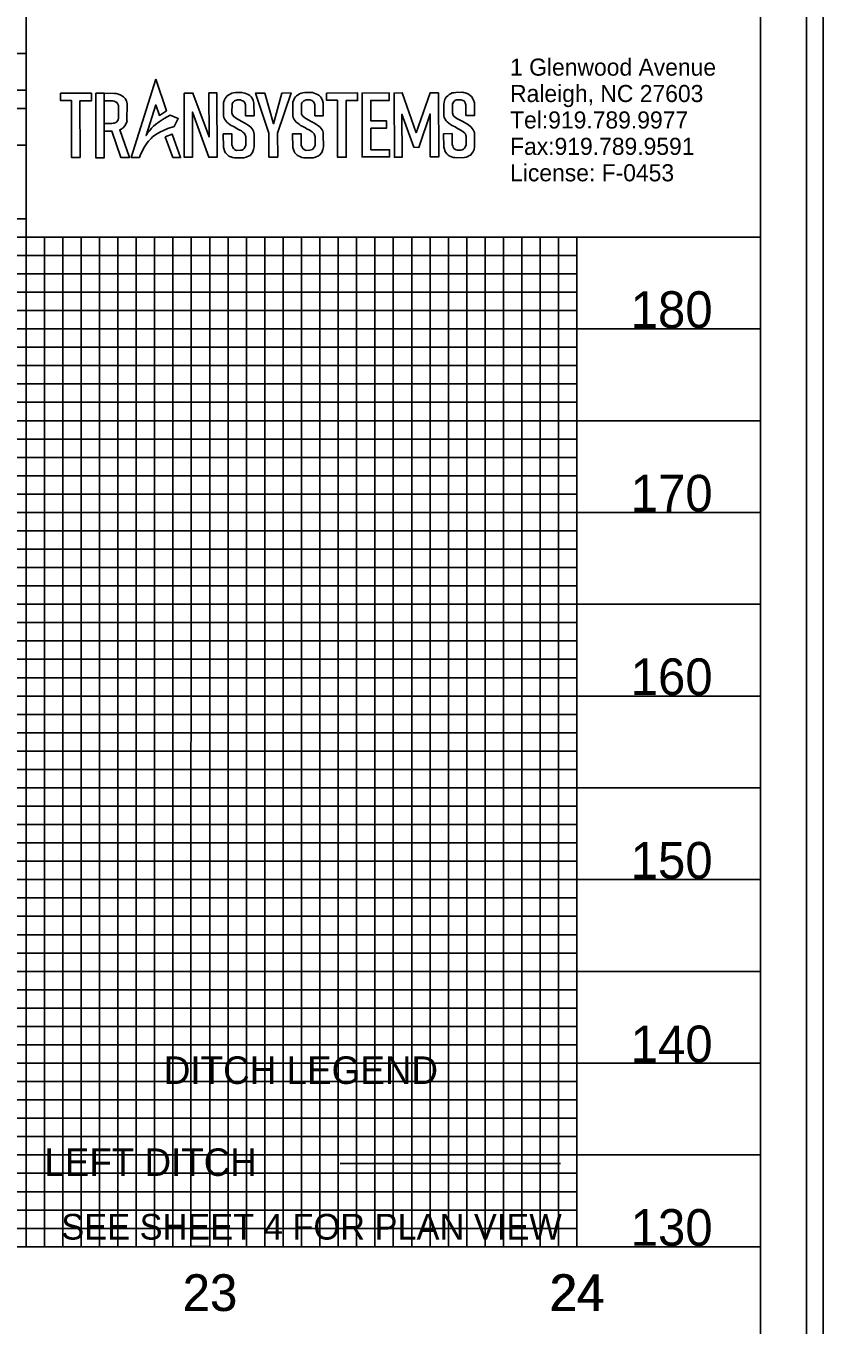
# Model space of a CAD drawing. Extents: x 1779926 to 1781610, y 620464 to 621564.
# Drawn here: x 1781392.9 to 1781610, y 621017.9 to 621371.7 of the extents above; entities that cross this region are included whole.
import ezdxf

# ---------------------------------------------------------------- set-up
doc = ezdxf.new("R2010")
doc.units = 0
for name, color, linetype in [('Default', 7, 'Continuous'), ('Exist Vertical Profile Horizontal Axis Label Major', 7, 'Continuous'), ('Exist Vertical Profile Vertical Axis Label', 7, 'Continuous'), ('Old_Level_2', 7, 'Continuous'), ('Old_Level_58', 7, 'Continuous'), ('Prop DSN Text', 7, 'Continuous'), ('Prop Grid Mask', 7, 'Continuous'), ('Prop PFL Ditch Label CELL', 7, 'Continuous'), ('Scratch_Level_0', 7, 'Continuous'), ('Sheet DOT Grid CELL', 7, 'Continuous'), ('Sheet Layout Profile Border Port 1', 7, 'Continuous'), ('Sheet Plot Border Inside CELL', 7, 'Continuous'), ('Sheet Plot Border Outside CELL', 7, 'Continuous'), ('Sheet Profile CELL', 7, 'Continuous'), ('Sheet Profile Grid Major CELL', 7, 'Continuous'), ('Sheet Profile Grid Middle CELL', 7, 'Continuous'), ('Sheet Profile Grid Minor CELL', 7, 'Continuous')]:
    doc.layers.add(name, color=color, linetype=linetype)

msp = doc.modelspace()

# ---------------------------------------------------------------- linework, layer by layer
at = {"layer": 'Default'}
for points in [[(1781428.25, 621357.21), (1781421.58, 621335.88), (1781423.81, 621335.89), (1781424.15, 621336.73), (1781424.72, 621337.89), (1781425.03, 621338.52), (1781425.41, 621339.06), (1781425.93, 621339.82), (1781426.26, 621340.28), (1781426.64, 621340.68), (1781427.02, 621341.07), (1781427.51, 621341.57), (1781427.92, 621341.84), (1781428.33, 621342.17), (1781428.89, 621342.49), (1781429.38, 621342.77), (1781430.6, 621343.34), (1781431.6, 621343.75), (1781433.24, 621344.31), (1781434.38, 621346.45), (1781432.2, 621347.41), (1781430.57, 621346.52), (1781429.19, 621345.62), (1781428.21, 621344.82), (1781427.69, 621344.39), (1781427.15, 621343.83), (1781426.62, 621343.26), (1781426.22, 621342.83), (1781425.84, 621342.19), (1781425.63, 621341.83), (1781428.26, 621350.2), (1781429.26, 621347.31), (1781431.16, 621348.57)], [(1781402.29, 621353.37), (1781410.75, 621353.37), (1781410.75, 621351.3), (1781407.64, 621351.3), (1781407.66, 621335.88), (1781405.31, 621335.87), (1781405.29, 621351.4), (1781402.32, 621351.4)], [(1781411.91, 621353.36), (1781414.22, 621353.36), (1781414.24, 621335.8), (1781411.92, 621335.8)], [(1781414.22, 621351.28), (1781416.61, 621351.28), (1781416.91, 621351.23), (1781417.32, 621351.07), (1781417.64, 621350.85), (1781417.87, 621350.58), (1781418.03, 621350.25), (1781418.15, 621349.99), (1781418.15, 621349.41), (1781418.16, 621346.92), (1781418.1, 621346.59), (1781418.01, 621346.14), (1781417.88, 621345.85), (1781417.68, 621345.59), (1781417.41, 621345.38), (1781416.99, 621345.23), (1781416.66, 621345.18), (1781416.34, 621345.14), (1781414.23, 621345.13), (1781414.24, 621343.02), (1781416.35, 621343.03), (1781418.72, 621335.87), (1781421.13, 621335.9), (1781418.48, 621343.44), (1781418.86, 621343.57), (1781419.4, 621343.97), (1781419.89, 621344.5), (1781420.23, 621345.14), (1781420.45, 621345.77), (1781420.43, 621345.96), (1781420.48, 621350.52), (1781420.27, 621351.27), (1781419.91, 621351.94), (1781419.5, 621352.42), (1781418.8, 621352.89), (1781418.12, 621353.12), (1781417.45, 621353.34), (1781417.04, 621353.34), (1781414.22, 621353.36)], [(1781436.02, 621353.4), (1781436.03, 621335.94), (1781438.27, 621335.94), (1781438.26, 621348.22), (1781442.71, 621335.92), (1781444.96, 621335.95), (1781444.94, 621353.45), (1781442.76, 621353.45), (1781442.78, 621341.47), (1781438.37, 621353.4)], [(1781452.72, 621347.23), (1781455.03, 621347.23), (1781455.02, 621350.71), (1781454.83, 621351.41), (1781454.55, 621352), (1781454.25, 621352.39), (1781453.88, 621352.74), (1781453.44, 621353.03), (1781453.01, 621353.2), (1781453.01, 621353.2), (1781452.55, 621353.39), (1781452.07, 621353.52), (1781451.75, 621353.6), (1781450, 621353.56), (1781449.47, 621353.47), (1781449.02, 621353.39), (1781448.55, 621353.15), (1781448.15, 621352.94), (1781447.76, 621352.65), (1781447.45, 621352.34), (1781447.2, 621351.98), (1781447.01, 621351.58), (1781446.75, 621350.88), (1781446.7, 621350.37), (1781446.7, 621347.2), (1781446.82, 621346.72), (1781447.05, 621346.23), (1781447.34, 621345.82), (1781447.63, 621345.51), (1781448.08, 621345.16), (1781448.54, 621344.81), (1781448.82, 621344.59), (1781449.3, 621344.37), (1781449.79, 621344.14), (1781450.18, 621343.89), (1781450.62, 621343.6), (1781451.15, 621343.34), (1781451.58, 621343.12), (1781452.01, 621342.8), (1781452.32, 621342.51), (1781452.57, 621342.27), (1781452.72, 621341.79), (1781452.82, 621341.49), (1781452.78, 621339.25), (1781452.62, 621338.77), (1781452.38, 621338.35), (1781452.05, 621338.06), (1781451.69, 621337.9), (1781451.35, 621337.83), (1781450.39, 621337.81), (1781450.07, 621337.9), (1781449.74, 621338.09), (1781449.41, 621338.28), (1781449.27, 621338.62), (1781449.13, 621338.95), (1781449.01, 621339.22), (1781448.98, 621342.33), (1781446.64, 621342.31), (1781446.68, 621338.6), (1781446.8, 621338.31), (1781447.07, 621337.45), (1781447.24, 621337.16), (1781447.5, 621336.84), (1781447.88, 621336.47), (1781448.18, 621336.27), (1781448.62, 621336.09), (1781448.78, 621336.02), (1781449.2, 621335.84), (1781449.74, 621335.79), (1781450.13, 621335.75), (1781452.27, 621335.8), (1781452.87, 621335.95), (1781453.69, 621336.32), (1781453.97, 621336.45), (1781454.6, 621337.24), (1781454.93, 621338.02), (1781455.08, 621338.73), (1781455.03, 621342.16), (1781455.02, 621342.63), (1781454.89, 621343), (1781454.7, 621343.36), (1781454.16, 621344.12), (1781453.45, 621344.67), (1781452.48, 621345.25), (1781451.73, 621345.7), (1781450.27, 621346.46), (1781449.52, 621347.03), (1781449.19, 621347.45), (1781449.11, 621347.73), (1781449.03, 621348.01), (1781449.08, 621350.45), (1781449.2, 621350.7), (1781449.33, 621350.96), (1781449.51, 621351.11), (1781449.74, 621351.3), (1781450, 621351.41), (1781450.25, 621351.52), (1781450.4, 621351.49), (1781450.42, 621351.56), (1781451.38, 621351.55), (1781451.65, 621351.44), (1781451.93, 621351.33), (1781452.21, 621351.22), (1781452.34, 621351.03), (1781452.52, 621350.75), (1781452.61, 621350.47), (1781452.71, 621350.2), (1781452.7, 621349.89)], [(1781457.99, 621353.41), (1781455.45, 621353.41), (1781459.07, 621342.52), (1781459.1, 621335.98), (1781461.49, 621335.99), (1781461.46, 621342.48), (1781465.12, 621353.45), (1781462.62, 621353.38), (1781460.31, 621345.04)], [(1781471.59, 621347.24), (1781473.9, 621347.25), (1781473.89, 621350.72), (1781473.7, 621351.43), (1781473.42, 621352.02), (1781473.12, 621352.41), (1781472.75, 621352.76), (1781472.31, 621353.04), (1781471.88, 621353.22), (1781471.88, 621353.22), (1781471.43, 621353.41), (1781470.94, 621353.53), (1781470.62, 621353.61), (1781468.87, 621353.58), (1781468.34, 621353.49), (1781467.89, 621353.41), (1781467.43, 621353.17), (1781467.02, 621352.96), (1781466.63, 621352.67), (1781466.32, 621352.36), (1781466.08, 621351.99), (1781465.88, 621351.6), (1781465.63, 621350.9), (1781465.58, 621350.39), (1781465.58, 621347.22), (1781465.69, 621346.74), (1781465.92, 621346.25), (1781466.21, 621345.84), (1781466.51, 621345.53), (1781466.96, 621345.18), (1781467.41, 621344.83), (1781467.69, 621344.61), (1781468.18, 621344.39), (1781468.66, 621344.16), (1781469.05, 621343.91), (1781469.49, 621343.62), (1781470.02, 621343.36), (1781470.45, 621343.14), (1781470.88, 621342.82), (1781471.19, 621342.53), (1781471.44, 621342.29), (1781471.59, 621341.81), (1781471.69, 621341.51), (1781471.65, 621339.27), (1781471.49, 621338.79), (1781471.25, 621338.37), (1781470.92, 621338.08), (1781470.56, 621337.92), (1781470.22, 621337.84), (1781469.26, 621337.82), (1781468.94, 621337.91), (1781468.61, 621338.11), (1781468.28, 621338.3), (1781468.14, 621338.64), (1781468, 621338.97), (1781467.88, 621339.24), (1781467.85, 621342.35), (1781465.51, 621342.32), (1781465.55, 621338.61), (1781465.67, 621338.33), (1781465.94, 621337.47), (1781466.12, 621337.18), (1781466.37, 621336.86), (1781466.75, 621336.48), (1781467.05, 621336.29), (1781467.49, 621336.11), (1781467.65, 621336.04), (1781468.08, 621335.86), (1781468.61, 621335.81), (1781469, 621335.77), (1781471.15, 621335.82), (1781471.74, 621335.96), (1781472.57, 621336.34), (1781472.85, 621336.46), (1781473.47, 621337.25), (1781473.8, 621338.04), (1781473.96, 621338.75), (1781473.9, 621342.17), (1781473.9, 621342.65), (1781473.76, 621343.02), (1781473.57, 621343.38), (1781473.03, 621344.13), (1781472.33, 621344.69), (1781471.35, 621345.27), (1781470.61, 621345.71), (1781469.14, 621346.48), (1781468.39, 621347.04), (1781468.06, 621347.46), (1781467.98, 621347.75), (1781467.91, 621348.03), (1781467.95, 621350.46), (1781468.08, 621350.72), (1781468.2, 621350.97), (1781468.38, 621351.13), (1781468.61, 621351.32), (1781468.87, 621351.43), (1781469.13, 621351.54), (1781469.27, 621351.51), (1781469.29, 621351.58), (1781470.25, 621351.57), (1781470.52, 621351.46), (1781470.8, 621351.35), (1781471.08, 621351.24), (1781471.21, 621351.04), (1781471.39, 621350.77), (1781471.49, 621350.49), (1781471.58, 621350.21), (1781471.57, 621349.91)], [(1781474.74, 621353.43), (1781483.21, 621353.44), (1781483.21, 621351.37), (1781480.1, 621351.36), (1781480.12, 621335.94), (1781477.77, 621335.94), (1781477.75, 621351.47), (1781474.78, 621351.46)], [(1781491.82, 621353.44), (1781484.43, 621353.43), (1781484.45, 621336.01), (1781491.92, 621336.01), (1781491.92, 621337.98), (1781486.87, 621337.98), (1781486.87, 621343.82), (1781491.08, 621343.83), (1781491.08, 621345.9), (1781486.83, 621345.9), (1781486.83, 621351.4), (1781491.84, 621351.4)], [(1781499.19, 621342.59), (1781495.38, 621353.51), (1781493.17, 621353.41), (1781493.25, 621335.95), (1781495.36, 621335.96), (1781495.31, 621347.63), (1781498.57, 621338.65), (1781499.92, 621338.61), (1781502.99, 621347.75), (1781503.03, 621336.02), (1781505.32, 621336.03), (1781505.25, 621353.45), (1781502.95, 621353.44)], [(1781512.72, 621347.28), (1781515.03, 621347.28), (1781515.03, 621350.76), (1781514.83, 621351.47), (1781514.55, 621352.06), (1781514.25, 621352.45), (1781513.88, 621352.8), (1781513.44, 621353.08), (1781513.02, 621353.26), (1781513.02, 621353.26), (1781512.56, 621353.45), (1781512.08, 621353.57), (1781511.76, 621353.65), (1781510.01, 621353.61), (1781509.48, 621353.52), (1781509.02, 621353.45), (1781508.56, 621353.21), (1781508.15, 621352.99), (1781507.76, 621352.71), (1781507.45, 621352.4), (1781507.21, 621352.03), (1781507.01, 621351.64), (1781506.76, 621350.94), (1781506.71, 621350.42), (1781506.71, 621347.26), (1781506.82, 621346.78), (1781507.05, 621346.29), (1781507.34, 621345.87), (1781507.64, 621345.57), (1781508.09, 621345.22), (1781508.54, 621344.87), (1781508.83, 621344.65), (1781509.31, 621344.42), (1781509.79, 621344.2), (1781510.18, 621343.95), (1781510.62, 621343.66), (1781511.15, 621343.39), (1781511.58, 621343.17), (1781512.01, 621342.86), (1781512.32, 621342.56), (1781512.57, 621342.33), (1781512.73, 621341.85), (1781512.82, 621341.55), (1781512.79, 621339.31), (1781512.62, 621338.83), (1781512.38, 621338.41), (1781512.05, 621338.12), (1781511.7, 621337.95), (1781511.36, 621337.88), (1781510.39, 621337.86), (1781510.07, 621337.95), (1781509.74, 621338.15), (1781509.41, 621338.34), (1781509.27, 621338.67), (1781509.13, 621339.01), (1781509.02, 621339.28), (1781508.98, 621342.39), (1781506.64, 621342.36), (1781506.69, 621338.65), (1781506.8, 621338.37), (1781507.07, 621337.51), (1781507.25, 621337.21), (1781507.5, 621336.9), (1781507.88, 621336.52), (1781508.19, 621336.33), (1781508.62, 621336.15), (1781508.78, 621336.08), (1781509.21, 621335.9), (1781509.74, 621335.85), (1781510.14, 621335.81), (1781512.28, 621335.86), (1781512.87, 621336), (1781513.7, 621336.38), (1781513.98, 621336.5), (1781514.6, 621337.29), (1781514.93, 621338.08), (1781515.09, 621338.79), (1781515.04, 621342.21), (1781515.03, 621342.68), (1781514.9, 621343.06), (1781514.71, 621343.41), (1781514.17, 621344.17), (1781513.46, 621344.73), (1781512.48, 621345.31), (1781511.74, 621345.75), (1781510.28, 621346.52), (1781509.52, 621347.08), (1781509.19, 621347.5), (1781509.12, 621347.79), (1781509.04, 621348.07), (1781509.08, 621350.5), (1781509.21, 621350.76), (1781509.33, 621351.01), (1781509.51, 621351.16), (1781509.74, 621351.36), (1781510, 621351.47), (1781510.26, 621351.58), (1781510.41, 621351.55), (1781510.42, 621351.62), (1781511.38, 621351.6), (1781511.66, 621351.49), (1781511.93, 621351.39), (1781512.21, 621351.28), (1781512.34, 621351.08), (1781512.53, 621350.8), (1781512.62, 621350.53), (1781512.71, 621350.25), (1781512.7, 621349.95)], [(1781430.86, 621341.51), (1781432.78, 621342.27), (1781435.04, 621335.84), (1781432.94, 621335.91)]]:
    msp.add_lwpolyline(points, close=True, dxfattribs=at)
at = {"layer": 'Old_Level_58'}
msp.add_lwpolyline([(1781392.96, 621378.13), (1781592.95, 621378.13), (1781592.95, 621314.19), (1781392.96, 621314.19)], close=True, dxfattribs=at)
at = {"layer": 'Prop Grid Mask'}
for points in [[(1781392.96, 621099.19), (1781542.96, 621099.19), (1781542.96, 621074.19), (1781392.96, 621074.19)], [(1781392.96, 621074.19), (1781542.96, 621074.19), (1781542.96, 621049.19), (1781392.96, 621049.19)], [(1781542.96, 621049.19), (1781397.96, 621049.19), (1781397.96, 621039.19), (1781542.96, 621039.19)]]:
    msp.add_lwpolyline(points, close=True, dxfattribs=at)
at = {"layer": 'Prop PFL Ditch Label CELL'}
msp.add_line((1781478.51, 621061.89), (1781538.51, 621061.89), dxfattribs=at)
msp.add_line((1781478.51, 621061.89), (1781538.51, 621061.89), dxfattribs=at)
at = {"layer": 'Scratch_Level_0'}
msp.add_lwpolyline([(1780142.96, 621039.18), (1780142.96, 621239.19), (1780092.96, 621239.19), (1780092.96, 621264.19), (1780142.96, 621289.19), (1780142.96, 621539.18), (1781392.96, 621539.18), (1781392.96, 621314.18), (1781542.96, 621314.18), (1781542.96, 621039.18)], close=True, dxfattribs=at)
at = {"layer": 'Sheet DOT Grid CELL'}
for p, q in [((1781392.96, 621039.19), (1781392.96, 621401.64)), ((1781442.96, 621039.19), (1781442.96, 621314.19)), ((1781492.96, 621039.19), (1781492.96, 621314.19)), ((1781542.96, 621039.19), (1781542.96, 621314.19)), ((1781592.96, 621289.19), (1780092.96, 621289.19)), ((1781592.96, 621239.19), (1780092.96, 621239.19)), ((1781592.96, 621189.19), (1780092.96, 621189.19)), ((1781592.96, 621139.19), (1780092.96, 621139.19)), ((1781592.96, 621089.19), (1780092.96, 621089.19))]:
    msp.add_line(p, q, dxfattribs=at)
at = {"layer": 'Sheet Layout Profile Border Port 1'}
msp.add_lwpolyline([(1780142.96, 621378.14), (1780142.96, 621039.19), (1781542.96, 621039.19), (1781542.96, 621314.19)], dxfattribs=at)
at = {"layer": 'Sheet Plot Border Inside CELL'}
msp.add_lwpolyline([(1779938.96, 620486.64), (1781605.46, 620486.64), (1781605.46, 621541.74), (1779938.96, 621541.74)], close=True, dxfattribs=at)
at = {"layer": 'Sheet Plot Border Outside CELL'}
msp.add_lwpolyline([(1779925.96, 620464.19), (1781609.96, 620464.19), (1781609.96, 621564.19), (1779925.96, 621564.19)], close=True, dxfattribs=at)
at = {"layer": 'Sheet Profile CELL'}
msp.add_line((1780092.96, 621039.19), (1781592.96, 621039.19), dxfattribs=at)
msp.add_lwpolyline([(1781592.96, 621539.19), (1780092.96, 621539.19), (1780092.96, 620489.19), (1781592.96, 620489.19)], close=True, dxfattribs=at)
at = {"layer": 'Sheet Profile Grid Major CELL'}
for points in [[(1781142.96, 621039.19), (1781192.96, 621039.19), (1781192.96, 621539.19), (1781242.96, 621539.19), (1781242.96, 621039.19), (1781292.96, 621039.19), (1781292.96, 621539.19), (1781342.96, 621539.19), (1781342.96, 621039.19), (1781392.96, 621039.19), (1781392.96, 621539.19), (1781419.26, 621539.19)], [(1781542.96, 621314.19), (1781542.96, 621039.19), (1781592.96, 621039.19), (1781592.96, 621389.19)], [(1781392.91, 621339.19), (1780092.96, 621339.19), (1780092.96, 621289.19), (1781592.96, 621289.19)], [(1781442.96, 621314.19), (1781442.96, 621039.19), (1781492.96, 621039.19), (1781492.96, 621039.19), (1781492.96, 621314.19)], [(1781592.96, 621239.19), (1780092.96, 621239.19), (1780092.96, 621189.19), (1781592.96, 621189.19)], [(1781592.96, 621139.19), (1780092.96, 621139.19), (1780092.96, 621139.19), (1780092.96, 621089.19), (1781592.96, 621089.19)]]:
    msp.add_lwpolyline(points, dxfattribs=at)
at = {"layer": 'Sheet Profile Grid Middle CELL'}
for points in [[(1781117.96, 621539.19), (1781167.96, 621539.19), (1781167.96, 621039.19), (1781217.96, 621039.19), (1781217.96, 621539.19), (1781267.96, 621539.19), (1781267.96, 621039.19), (1781317.96, 621039.19), (1781317.96, 621539.19), (1781367.96, 621539.19), (1781367.96, 621039.19), (1781417.96, 621039.19), (1781417.96, 621314.19)], [(1781392.91, 621364.19), (1780092.96, 621364.19), (1780092.96, 621314.19), (1781417.96, 621314.19)], [(1781417.96, 621314.19), (1781592.96, 621314.19)], [(1781417.96, 621301.99), (1781417.96, 621039.19), (1781467.96, 621039.19), (1781467.96, 621314.19)], [(1781467.96, 621301.99), (1781467.96, 621039.19), (1781517.96, 621039.19), (1781517.96, 621314.19)], [(1781592.96, 621264.19), (1780092.96, 621264.19), (1780092.96, 621214.19), (1781592.96, 621214.19)], [(1781592.96, 621164.19), (1780092.96, 621164.19), (1780092.96, 621114.19), (1781592.96, 621114.19)], [(1781592.96, 621064.19), (1780092.96, 621064.19)]]:
    msp.add_lwpolyline(points, dxfattribs=at)
at = {"layer": 'Sheet Profile Grid Minor CELL'}
for p, q in [((1781392.96, 621354.19), (1780142.96, 621354.19)), ((1780142.96, 621349.19), (1781392.96, 621349.19)), ((1781542.96, 621304.19), (1780142.96, 621304.19)), ((1780142.96, 621299.19), (1781542.96, 621299.19)), ((1781542.96, 621294.19), (1780142.96, 621294.19)), ((1780142.96, 621284.19), (1781542.96, 621284.19)), ((1781542.96, 621279.19), (1780142.96, 621279.19)), ((1780142.96, 621274.19), (1781542.96, 621274.19)), ((1781542.96, 621269.19), (1780142.96, 621269.19)), ((1780142.96, 621259.19), (1781542.96, 621259.19)), ((1781542.96, 621254.19), (1780142.96, 621254.19)), ((1780142.96, 621249.19), (1781542.96, 621249.19)), ((1781542.96, 621244.19), (1780142.96, 621244.19)), ((1780142.96, 621234.19), (1781542.96, 621234.19)), ((1781542.96, 621229.19), (1780142.96, 621229.19)), ((1780142.96, 621224.19), (1781542.96, 621224.19)), ((1781542.96, 621219.19), (1780142.96, 621219.19)), ((1780142.96, 621209.19), (1781542.96, 621209.19)), ((1781542.96, 621204.19), (1780142.96, 621204.19)), ((1780142.96, 621199.19), (1781542.96, 621199.19)), ((1781542.96, 621194.19), (1780142.96, 621194.19)), ((1780142.96, 621184.19), (1781542.96, 621184.19)), ((1781542.96, 621179.19), (1780142.96, 621179.19)), ((1780142.96, 621174.19), (1781542.96, 621174.19)), ((1781542.96, 621169.19), (1780142.96, 621169.19)), ((1780142.96, 621159.19), (1781542.96, 621159.19)), ((1781542.96, 621154.19), (1780142.96, 621154.19)), ((1781542.96, 621149.19), (1780142.96, 621149.19)), ((1781542.96, 621144.19), (1780142.96, 621144.19)), ((1780142.96, 621134.19), (1781542.96, 621134.19)), ((1781542.96, 621129.19), (1780142.96, 621129.19)), ((1780142.96, 621124.19), (1781542.96, 621124.19)), ((1781542.96, 621119.19), (1780142.96, 621119.19)), ((1780142.96, 621109.19), (1781542.96, 621109.19)), ((1781542.96, 621104.19), (1780142.96, 621104.19)), ((1780142.96, 621099.19), (1781542.96, 621099.19)), ((1781542.96, 621094.19), (1780142.96, 621094.19)), ((1780142.96, 621084.19), (1781542.96, 621084.19)), ((1781542.96, 621079.19), (1780142.96, 621079.19)), ((1780142.96, 621074.19), (1781542.96, 621074.19)), ((1781542.96, 621069.19), (1780142.96, 621069.19)), ((1780142.96, 621059.19), (1781542.96, 621059.19)), ((1781542.96, 621054.19), (1780142.96, 621054.19)), ((1780142.96, 621049.19), (1781542.96, 621049.19))]:
    msp.add_line(p, q, dxfattribs=at)
for points in [[(1781392.91, 621319.19), (1780142.96, 621319.19), (1780142.96, 621309.19), (1781542.96, 621309.19)], [(1781397.96, 621314.19), (1781397.96, 621039.19), (1781402.96, 621039.19), (1781402.96, 621314.19)], [(1781407.96, 621314.19), (1781407.96, 621039.19), (1781412.96, 621039.19), (1781412.96, 621314.19)], [(1781422.96, 621314.19), (1781422.96, 621039.19), (1781422.96, 621039.19), (1781427.96, 621039.19), (1781432.96, 621039.19), (1781432.96, 621314.19)], [(1781427.96, 621314.19), (1781427.96, 621039.19)], [(1781437.94, 621314.19), (1781437.86, 621039.24), (1781442.86, 621039.24), (1781447.96, 621039.19), (1781447.96, 621314.19)], [(1781447.96, 621301.99), (1781447.96, 621039.19), (1781452.96, 621039.19), (1781452.96, 621314.19)], [(1781457.96, 621314.19), (1781457.96, 621039.19), (1781462.96, 621039.19), (1781462.96, 621314.19)], [(1781472.96, 621314.19), (1781472.96, 621039.19), (1781477.96, 621039.19), (1781477.96, 621314.19)], [(1781482.96, 621314.19), (1781482.96, 621039.19), (1781487.96, 621039.19), (1781487.96, 621314.19)], [(1781497.96, 621314.19), (1781497.96, 621039.19), (1781502.96, 621039.19), (1781502.96, 621314.19)], [(1781507.96, 621314.19), (1781507.96, 621039.19), (1781512.96, 621039.19), (1781512.96, 621314.19)], [(1781522.96, 621314.19), (1781522.96, 621039.19), (1781527.96, 621039.19), (1781527.96, 621314.19)], [(1781532.96, 621314.19), (1781532.96, 621039.19), (1781537.96, 621039.19), (1781537.96, 621314.19)], [(1781542.96, 621044.19), (1780142.96, 621044.19)]]:
    msp.add_lwpolyline(points, dxfattribs=at)

# ---------------------------------------------------------------- texts
at = {"layer": 'Exist Vertical Profile Horizontal Axis Label Major'}
for s, p in [('23', (1781435.57, 621021.69)), ('23', (1781435.63, 621021.69)), ('23', (1781435.63, 621021.69)), ('24', (1781535.41, 621021.69)), ('24', (1781535.69, 621021.69)), ('24', (1781535.69, 621021.69))]:
    msp.add_text(s, height=10, dxfattribs=at).set_placement(p)
at = {"layer": 'Exist Vertical Profile Vertical Axis Label'}
for s, p in [('180', (1781557.59, 621289.44)), ('170', (1781557.59, 621239.44)), ('160', (1781557.59, 621189.44)), ('150', (1781557.59, 621139.44)), ('140', (1781557.59, 621089.44)), ('130', (1781557.59, 621039.44))]:
    msp.add_text(s, height=10, dxfattribs=at).set_placement(p)
at = {"layer": 'Old_Level_2'}
for s, p in [('1 Glenwood Avenue', (1781524.75, 621358.16)), ('Raleigh, NC 27603', (1781524.75, 621350.97)), ('Tel:919.789.9977 ', (1781524.75, 621343.77)), ('Fax:919.789.9591', (1781524.75, 621336.58)), ('License: F-0453', (1781524.75, 621329.38))]:
    msp.add_text(s, height=4.6576, rotation=360, dxfattribs=at).set_placement(p)
at = {"layer": 'Prop DSN Text'}
msp.add_text('SEE SHEET 4 FOR PLAN VIEW', height=7, dxfattribs=at).set_placement((1781402.54, 621041.14))
at = {"layer": 'Prop PFL Ditch Label CELL'}
for s, height, p in [('DITCH LEGEND', 7.5, (1781430.46, 621083.54)), ('LEFT DITCH', 7.485, (1781397.96, 621058.49))]:
    msp.add_text(s, height=height, dxfattribs=at).set_placement(p)

doc.saveas('drawing.dxf')
